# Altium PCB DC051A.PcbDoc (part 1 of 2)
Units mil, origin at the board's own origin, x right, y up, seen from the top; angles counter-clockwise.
Board outline 3200 x 2600 mil, 4 copper layers (L1-TOP, L2-GND, L3-POWER, L4-BOTTOM), stack 58.217 mil thick; 95 components, 55 nets, 249 pads, 164 vias.
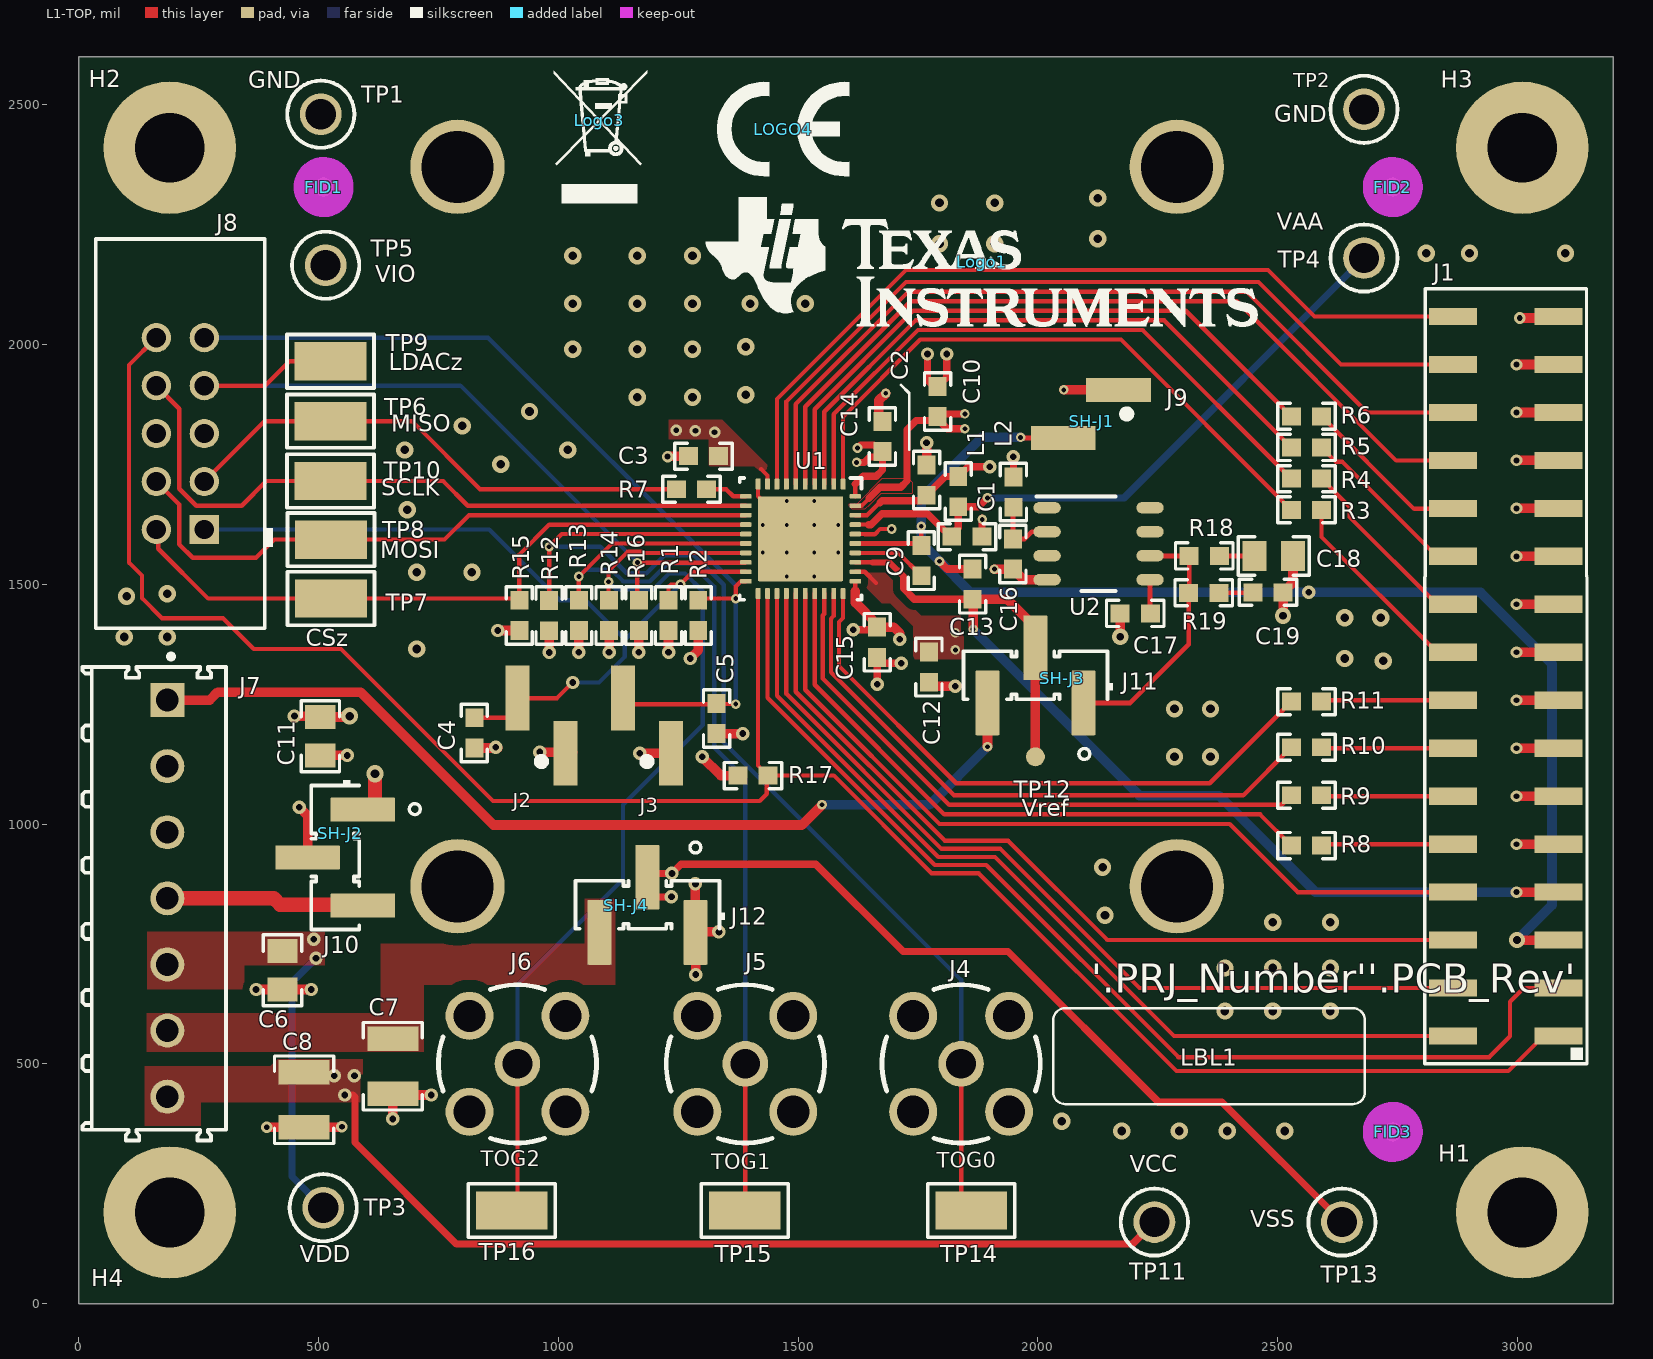
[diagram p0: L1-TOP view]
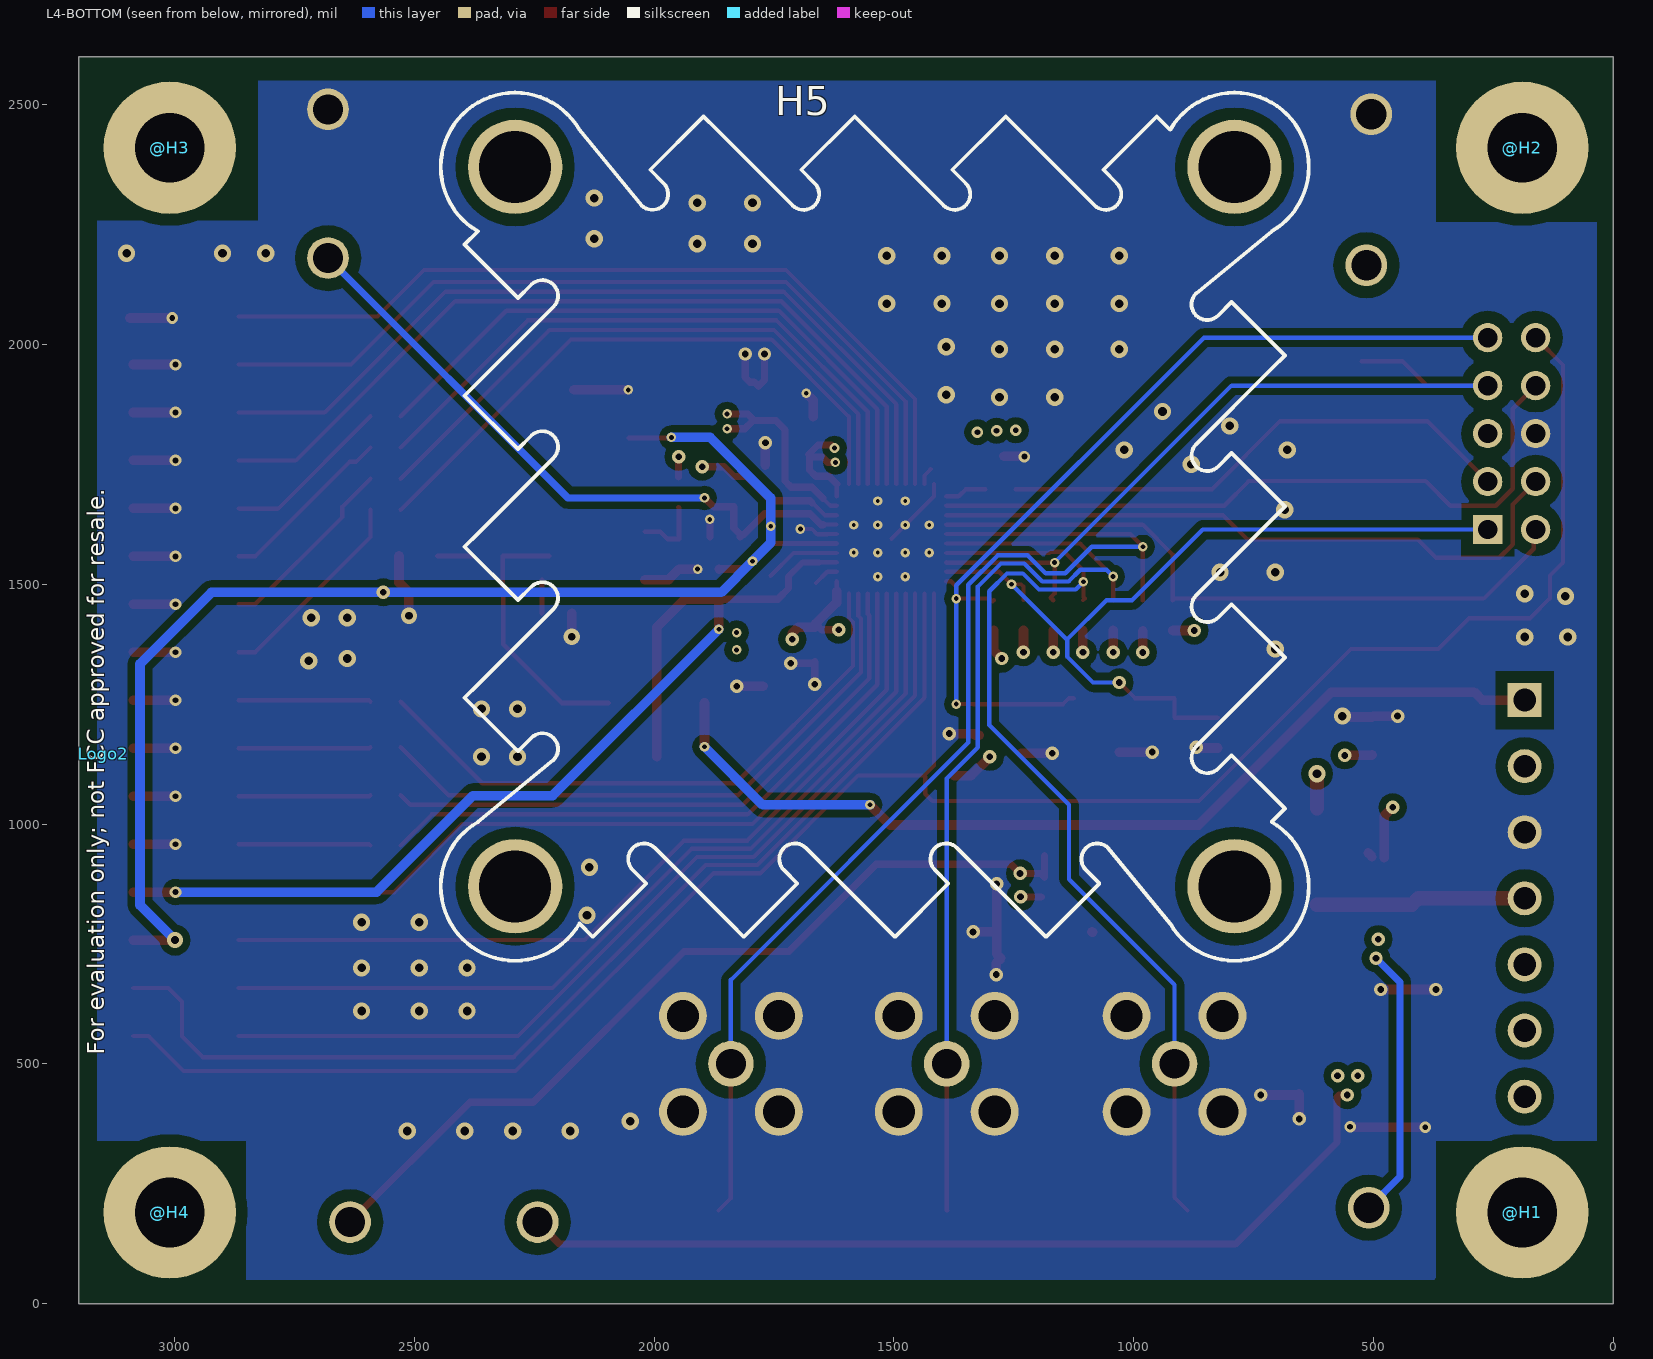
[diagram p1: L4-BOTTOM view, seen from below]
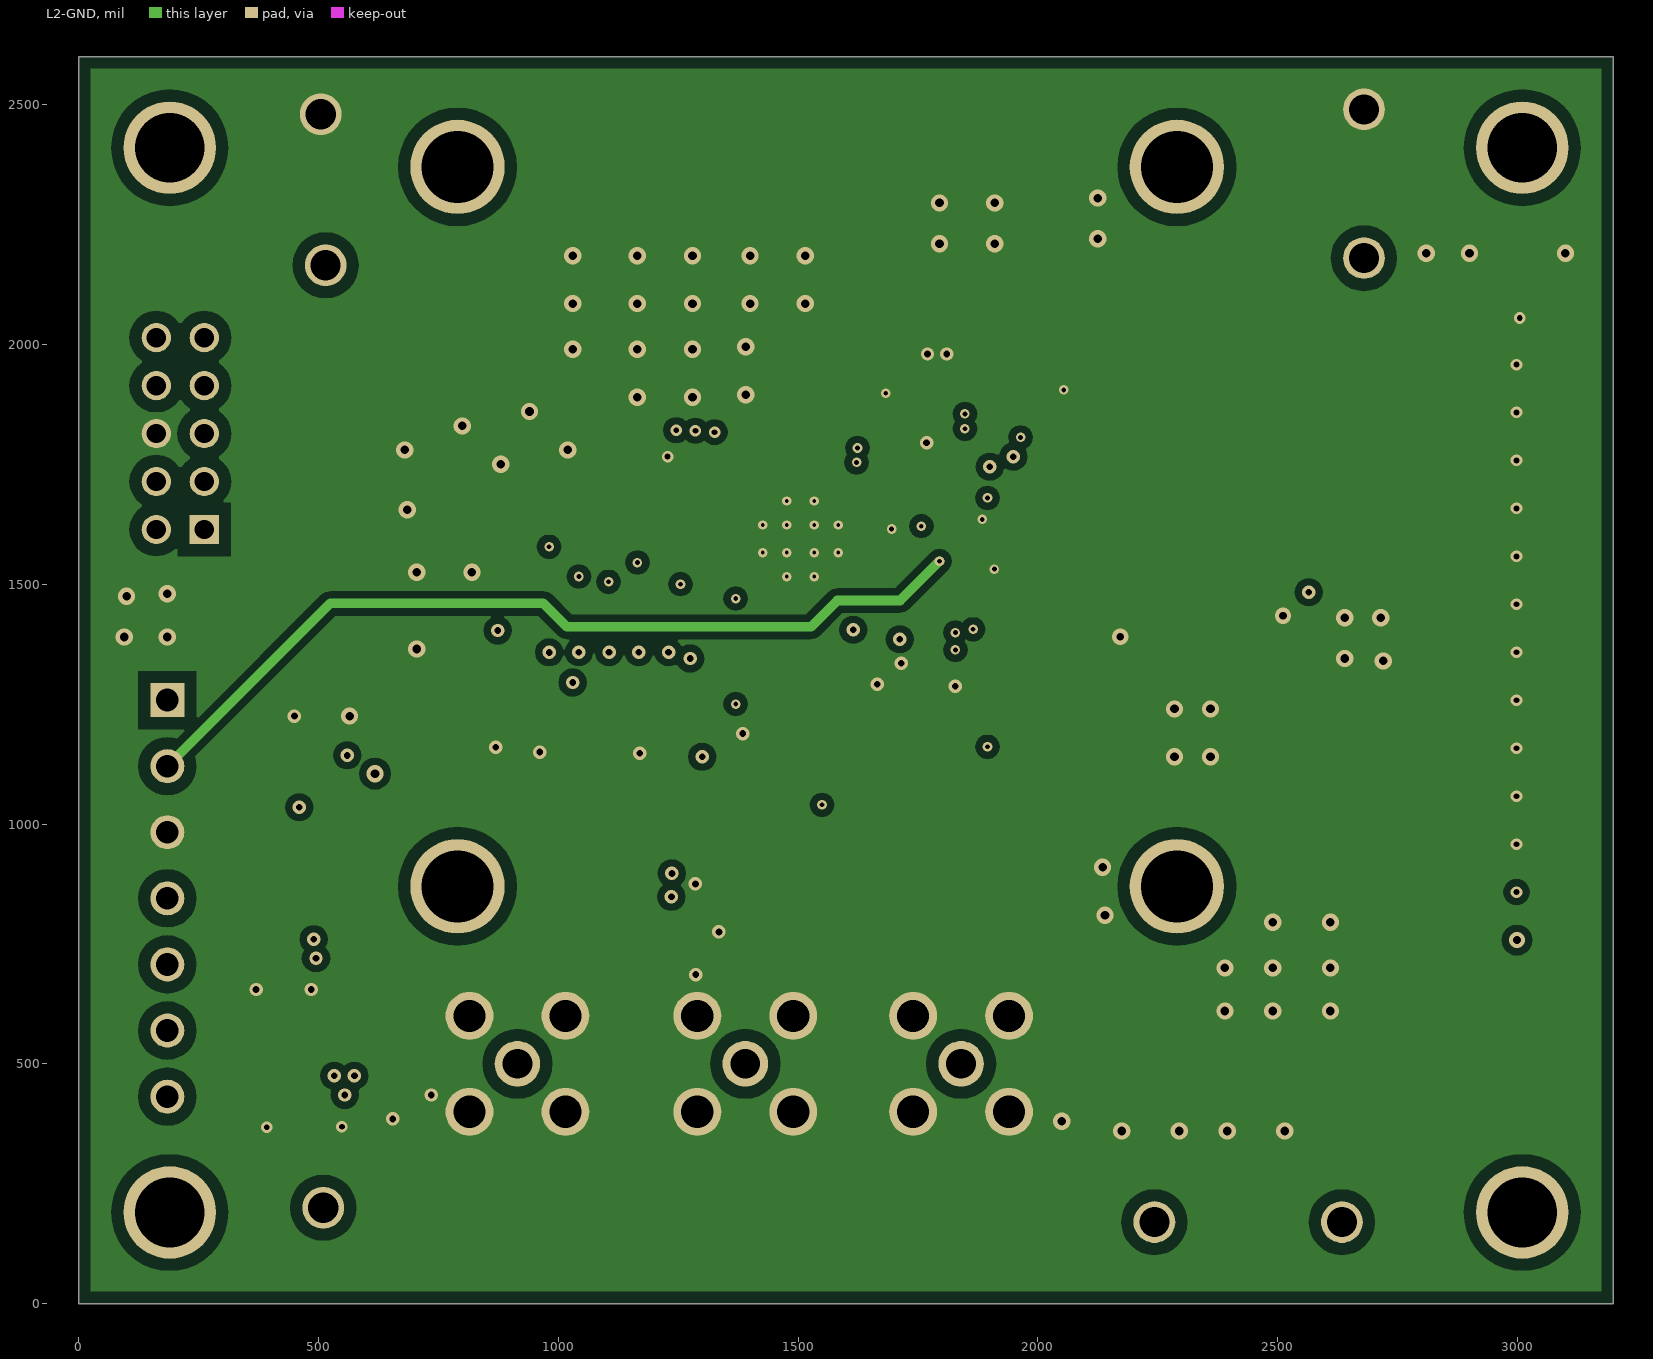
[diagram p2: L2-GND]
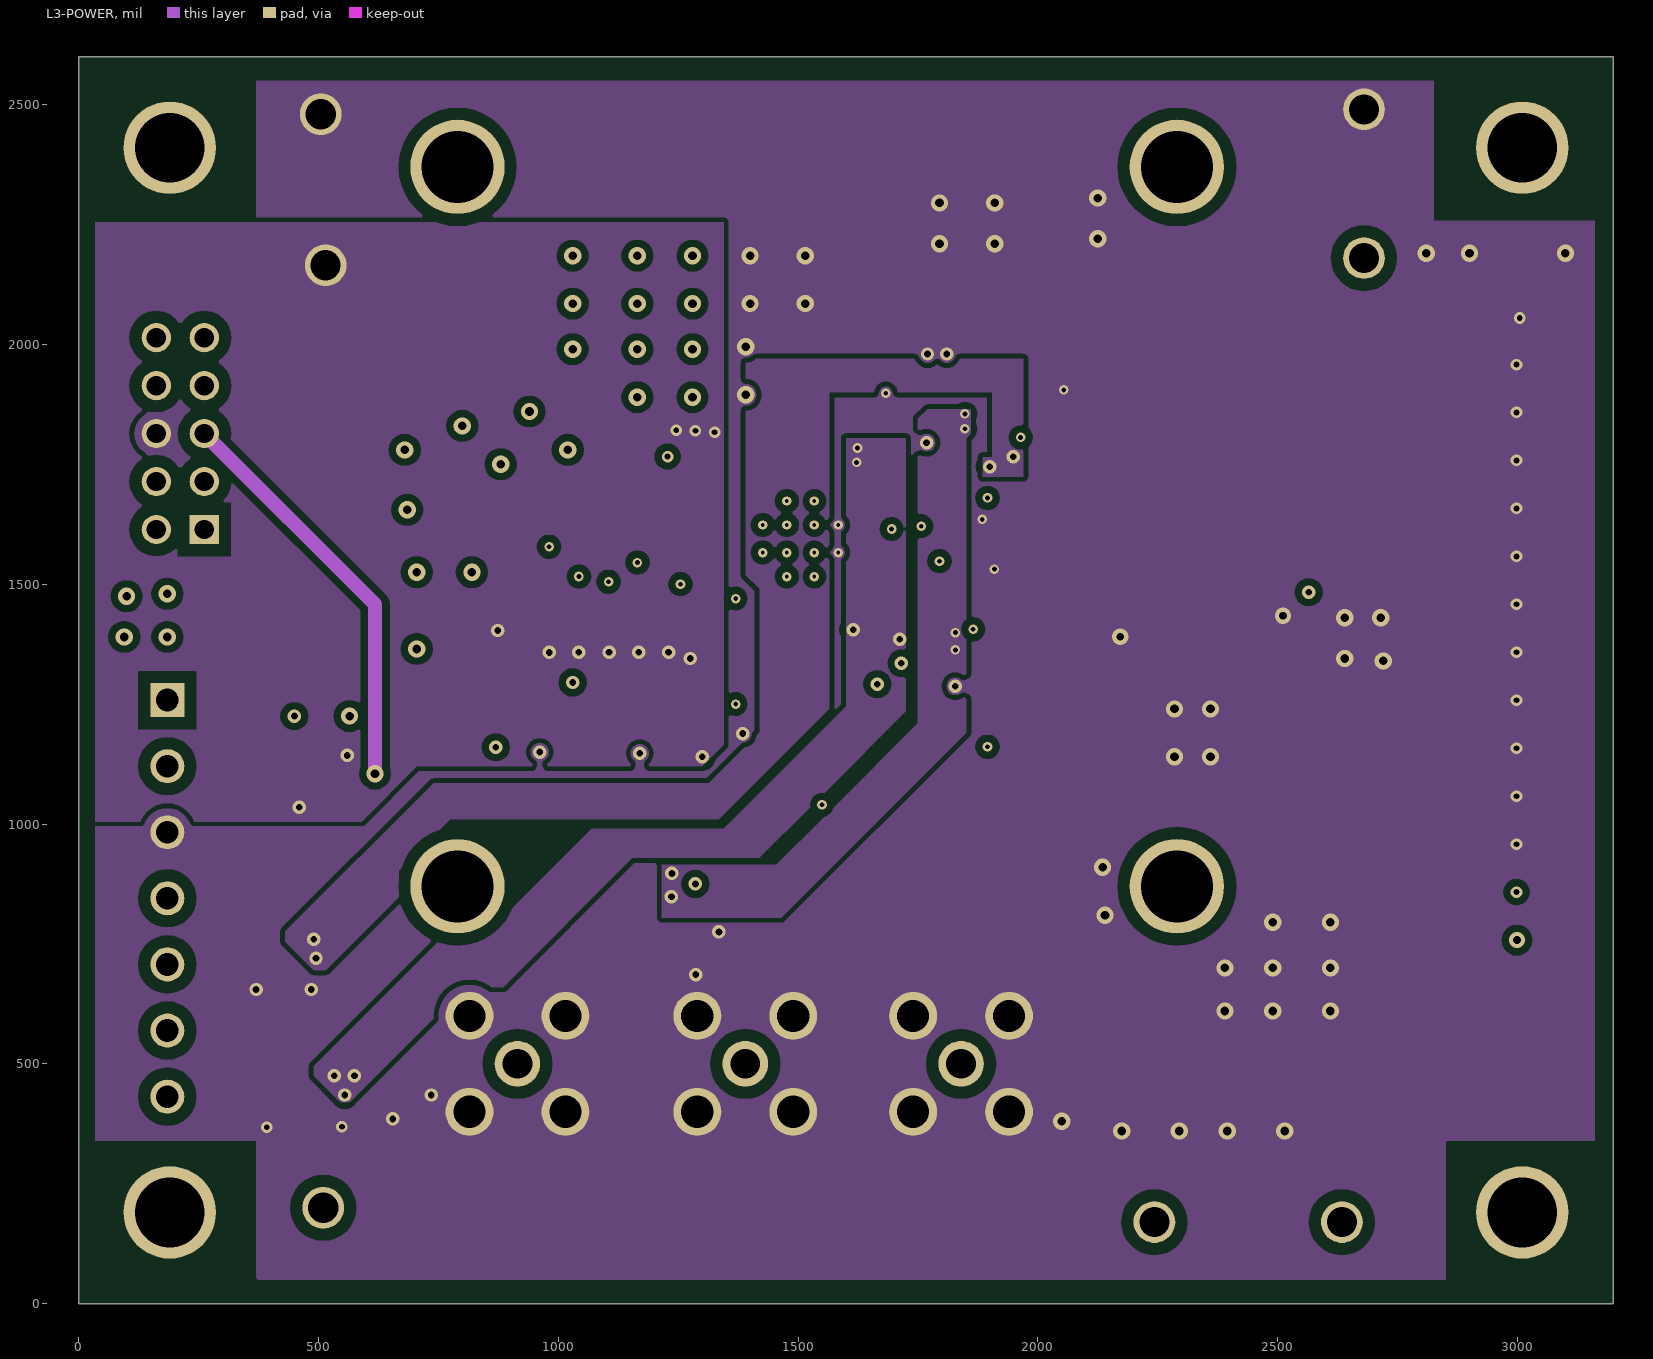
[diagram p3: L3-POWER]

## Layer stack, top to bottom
Top Solder: solder mask 0.4, Solder Resist, Dk 3.5
L1-TOP: signal copper 1.4
Dielectric1: core 10, FR-406, Dk 4.6
L2-GND: signal copper 1.417
Dielectric2: prepreg 32.6, FR-4, Dk 4.8
L3-POWER: signal copper 1.4
Dielectric3: core 10, FR-406, Dk 4.6
L4-BOTTOM: signal copper 1.4
Bottom Solder: solder mask 0.4, Solder Resist, Dk 3.5

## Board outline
0,0 0,2600 3200,2600 3200,0

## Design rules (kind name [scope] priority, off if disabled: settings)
AcuteAngle [All] p1: minimum=4.50000000000000E+0001 checktracksonly=FALSE
AssemblyTestPointUsage [All] p1: valid=2
BoardOutlineClearance BoardOutlineClearance_MountingHoles [OnCopper and InComponentClass('Mounting Holes')] p1: gap=40 ignorepadtopadclearanceinfootprint=FALSE
BoardOutlineClearance BoardOutlineClearance_Poly [OnCopper and IsPoly] p2: gap=25 ignorepadtopadclearanceinfootprint=FALSE
BoardOutlineClearance [OnCopper and Not InComponentClass('Logo') and not InComponentClass('FiducialMark') and not InRegion(1000,500,4000,800) and not InPoly] p3: gap=40 ignorepadtopadclearanceinfootprint=FALSE
Clearance Clearance_Keepouts [((IsTrack Or IsArc) And Not InPoly) And IsFree and IsKeepOut vs ((IsTrack Or IsArc) And Not InPoly) And IsFree and IsKeepOut] p1: gap=0 ignorepadtopadclearanceinfootprint=FALSE
Clearance Clearance_Poly [InPolygon] p2: gap=25 ignorepadtopadclearanceinfootprint=FALSE except(0: Arc-Hole Track-Hole SMDPad-Hole THPad-Hole Via-Hole Fill-Hole Poly-Hole Region-Hole Text-Hole; 10: Poly-Poly; 15: Track-Poly SMDPad-Poly Via-Poly)
Clearance [All] p3: gap=7.87 ignorepadtopadclearanceinfootprint=FALSE except(0: Arc-SMDPad Arc-Hole Track-Hole SMDPad-Hole THPad-Hole Via-Hole Fill-Hole Poly-Hole Region-Hole Text-Hole)
ComponentClearance ComponentClearance_MountingHoles_FiducialMarks [InComponentClass('Mounting Holes') vs InComponentClass('FiducialMark')] p1: gap=0 collisioncheckmode=3 verticalgap=10 showdistances=FALSE
ComponentClearance ComponentClearance_Shunt [InComponentClass('Header') vs InComponentClass('Shunt')] p2: gap=0 collisioncheckmode=3 verticalgap=0 showdistances=FALSE
ComponentClearance ComponentClearance_Logo [InComponentClass('Logo')] p3: gap=40 collisioncheckmode=3 verticalgap=10 showdistances=FALSE
ComponentClearance ComponentClearance_ScrewToNut [(HasFootprint('NY PMS 440 0025 PH')) vs (HasFootprint('Keystone_1902C'))] p4: gap=0 collisioncheckmode=3 verticalgap=0 showdistances=FALSE
ComponentClearance ComponentClearance_MountingHoles [InComponentClass('Mounting Holes')] p5: gap=0 collisioncheckmode=3 verticalgap=100000 showdistances=FALSE
ComponentClearance ComponentClearance_SmallPassives [HasFootprint('0201*') or HasFootprint('0402*') or HasFootprint('0508') or HasFootprint('0603*') or HasFootprint('0612') or HasFootprint('0805*') or HasFootprint('0815*') or HasFootprint('0830*') or HasFootprint('1206*') or HasFootprint('1210*') or HasFootprint('1808*') or HasFootprint('1812*') or HasFootprint('1825*') or HasFootprint('2010*') or HasFootprint('2220*') or HasFootprint('2225*') or HasFootprint('2512*') or HasFootprint('2728*') or HasFootprint('3518*') or HasFootprint('NY PMS 440 0025 PH') vs HasFootprint('0201*') or HasFootprint('0402*') or HasFootprint('0508') or HasFootprint('0603*') or HasFootprint('0612') or HasFootprint('0805*') or HasFootprint('0815*') or HasFootprint('0830*') or HasFootprint('1206*') or HasFootprint('1210*') or HasFootprint('1808*') or HasFootprint('1812*') or HasFootprint('1825*') or HasFootprint('2010*') or HasFootprint('2220*') or HasFootprint('2225*') or HasFootprint('2512*') or HasFootprint('2728*') or HasFootprint('3518*') or HasFootprint('Keystone_1902C')] p6: gap=14.96 collisioncheckmode=3 verticalgap=10 showdistances=FALSE
ComponentClearance ComponentClearance_THtoSMT [IsThruComponent vs IsSMTComponent] p7: gap=0 collisioncheckmode=3 verticalgap=0 showdistances=FALSE
ComponentClearance ComponentClearance_THtoTH [IsThruComponent vs IsThruComponent] p8: gap=30 collisioncheckmode=3 verticalgap=30 showdistances=FALSE
ComponentClearance [All] p9: gap=0 collisioncheckmode=3 verticalgap=10 showdistances=FALSE
DiffPairsRouting [All] p1: maxlimit=100 minlimit=10 mostfreqgap=10 toplayer_minwidth=15 toplayer_maxwidth=15 toplayer_prefwidth=15 midlayer1_minwidth=15 midlayer1_maxwidth=15 midlayer1_prefwidth=15 midlayer2_minwidth=15 midlayer2_maxwidth=15 midlayer2_prefwidth=15 bottomlayer_minwidth=15 bottomlayer_maxwidth=15 bottomlayer_prefwidth=15 maxuncoupledlength=1000
FabricationTestPointUsage TestPointUsage [All] p1: valid=2 allowmultiple=FALSE
FabricationTestpoint Testpoint [All] p1: side=3 testpointundercomponent=TRUE minsize=40 maxsize=100 preferedsize=60 minholesize=0 maxholesize=40 preferedholesize=32 testpointgrid=1 allowsidetop=TRUE allowsidebottom=TRUE usegrid=TRUE gridtolerance=0.01
FanoutControl Fanout_LCC [IsLCC] p1: bgadir=Out bgaviamode=Centered fanoutstyle=Auto fanoutdirection=Alternating viagrid=1 // Fanout_LCC (Default Rule)
FanoutControl Fanout_BGA [IsBGA] p2: bgadir=Out bgaviamode=Centered fanoutstyle=Auto fanoutdirection=Alternating viagrid=1 // Fanout_BGA (Default Rule)
FanoutControl Fanout_Default [All] p4: bgadir=Out bgaviamode=Centered fanoutstyle=Auto fanoutdirection=Alternating viagrid=1 // Fanout_Default (Default Rule)
FanoutControl Fanout_Small [(CompPinCount < 5)] p5: bgadir=Out bgaviamode=Centered fanoutstyle=Auto fanoutdirection=OutThenIn viagrid=1 // Fanout_Small (Default Rule)
Height [All] p1: minheight=0 maxheight=1400 prefheight=500
HoleSize [All] p1: absolutevalues=TRUE maxlimit=251 minlimit=7.87 maxpercent=80.000 minpercent=20.000
MinimumAnnularRing MinimumAnnularRing_ThermalPadVias [IsVia and InAnyComponent] p1: minimumring=5.91
MinimumAnnularRing [All] p2: minimumring=4
MinimumSolderMaskSliver MinimumSolderMaskSliver_Logo [InComponentClass('Logo') vs InComponentClass('Logo')] p1: minsoldermaskwidth=0.7
MinimumSolderMaskSliver [All] p2: minsoldermaskwidth=3.94
PlaneConnect [All] p1: planeconnectstyle=Relief reliefexpansion=10 reliefentries=4 reliefconductorwidth=10 reliefairgap=10
PolygonConnect [All] p1: connectstyle=Direct reliefconductorwidth=10 reliefentries=4 polygonreliefangle="90 Angle" airgapwidth=10
RoutingVias ThermalPadVias [IsVia and InAnyComponent] p1: holewidth=7.87 width=19.68 viastyle="Through Hole" minholewidth=7.87 minwidth=19.68 maxholewidth=12.99 maxwidth=23.62
RoutingVias [All] p2: holewidth=16 width=34 viastyle="Through Hole" minholewidth=7.87 minwidth=20 maxholewidth=40 maxwidth=65
SilkToBoardRegionClearance [Not ((IsComment or IsDesignator) And (Hide <> 'False')) and not InRegion(1000,500,4000,800)] p1:
SilkToSilkClearance SilkToSilkClearance_Pb-FreeLogo [(HasFootprint('Pb-Free_Overlay_Medium') OR HasFootprint('Pb-Free_Overlay_Small')) vs (HasFootprint('Pb-Free_Overlay_Medium') OR HasFootprint('Pb-Free_Overlay_Small'))] p1: silktosilkclearance=0
SilkToSilkClearance [All] p2: silktosilkclearance=3
SilkToSolderMaskClearance SilkToComponentPadClearance [(IsPad or IsFill or IsRegion) and InAnycomponent] p1: minsilkscreentomaskgap=3 clearancetoexposedcopper=TRUE
SilkToSolderMaskClearance "Silk to Solder Mask Opening" [All] p2: minsilkscreentomaskgap=3 clearancetoexposedcopper=FALSE
SolderMaskExpansion [All] p1: expansion=1.97
Width [All] p1: maxlimit=100 minlimit=6 preferedwidth=10 checkconnectedcopper=TRUE
14 further rules are at their usual default settings.

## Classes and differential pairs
component class Label: LBL1
component class DC051A_EVM_Hardware: !PCB @H1 @H2 @H3 @H4 FID1 FID2 FID3 H1 H2 H3 H4 H5 LBL1 Logo1 Logo2 Logo3 LOGO4 Logo4 LOGO? Logo? SH-J1 SH-J2 SH-J3 SH-J4 ZZ1 ZZ2 ZZ3 ZZ4
component class DC051A: C1 C2 C3 C4 C5 C6 C7 C8 C9 C10 C11 C12 C13 C14 C15 C16 C17 C18 C19 GND J1 J2 J3 J4 J5 J6 J7 J8 J9 J10 J11 J12 L1 L2 R1 R2 R3 R4 R5 R6 R7 R8 R9 R10 R11 R12 R13 R14 R15 R16 R17 R18 R19 TP1 TP2 TP3 TP4 TP5 TP6 TP7 TP8 TP9 TP10 TP11 TP12 TP13 TP14 TP15 TP16 U1 U2
component class Logo: Logo1
component class Header: J1 J2 J3 J9 J10 J11 J12
component class AssemblyNote: ZZ1 ZZ2 ZZ3 ZZ4
component class FiducialMark: FID1 FID2 FID3
component class Shunt: SH-J1 SH-J2 SH-J3 SH-J4

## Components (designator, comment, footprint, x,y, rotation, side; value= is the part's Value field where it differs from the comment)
@H1 "1891" Keystone_1891 190,190 r180 bottom
@H2 "1891" Keystone_1891 190,2410 r180 bottom
@H3 "1891" Keystone_1891 3010,2410 r180 bottom
@H4 "1891" Keystone_1891 3010,190 r180 bottom
C1 "C0603C105K4PACTU" 0603 1852,1599 r0 top value=1uF
C2 "C0603C104J4RACTU" 0603 1768,1717 r90 top value=0.1uF
C3 "C0603C104J4RACTU" 0603 1303,1767 r180 top value=0.1uF
C4 "C0603C105K4PACTU" 0603 825,1190 r270 top value=1uF
C5 "C0603C105K4PACTU" 0603 1330,1220 r270 top value=1uF
C6 "GRM21BC8YA106KE11L" 0805_HV 425,695 r270 top value=10uF
C7 "UMJ325KB7106KMHT" 1210_270 655,495 r270 top value=10uF
C8 "UMJ325KB7106KMHT" 1210_270 470,425 r270 top value=10uF
C9 "C0603C102K5RACTU" 0603 1757,1549 r90 top value=1000pF
C10 "C0603C105K4PACTU" 0603 1791,1881 r90 top value=1uF
C11 "GRM21BC8YA106KE11L" 0805_HV 504,1183 r90 top value=10uF
C12 "C0603C105K4PACTU" 0603 1773,1327 r270 top value=1uF
C13 "C0603C104J4RACTU" 0603 1864,1500 r90 top value=0.1uF
C14 "C0603C105K4PACTU" 0603 1676,1808 r90 top value=1uF
C15 "C0603C105K4PACTU" 0603 1665,1379 r270 top value=1uF
C16 "C1608X5R1E105K080AC" 0603 1948,1563 r270 top value=1uF
C17 "C1608X5R1E105K080AC" 0603 2203,1439 r180 top value=1uF
C18 "GRM21BC8YA106KE11L" 0805_HV 2492,1559 r0 top value=10uF
C19 "C1608X5R1E105K080AC" 0603 2480,1483 r0 top value=1uF
FID1 "Fiducial" Fiducial10-30 511,2328 r180 top
FID2 "Fiducial" Fiducial10-30 2740,2328 r180 top
FID3 "Fiducial" Fiducial10-30 2740,358 r180 top
H1 "29311" Keystone29311 3010,190 r0 top
H2 "29311" Keystone29311 190,2410 r0 top
H3 "29311" Keystone29311 3010,2410 r0 top
H4 "29311" Keystone29311 190,190 r0 top
H5 "500403B00000G" Aavid_500403B00000G 1540,1620 r0 bottom
J1 "TSM-116-01-T-DV-P" CONN_TSM-116-01-T-DV-P 2976,1308 r90 top
J2 "TSM-102-01-L-SV" Samtec_TSM-102-01-L-SV 965,1205 r180 top
J3 "TSM-102-01-L-SV" Samtec_TSM-102-01-L-SV 1185,1205 r180 top
J4 "142-0701-231" Johnson_142-0701-231 1840,500 r270 top
J5 "142-0701-231" Johnson_142-0701-231 1389.99,500 r180 top
J6 "142-0701-231" Johnson_142-0701-231 915,500 r90 top
J7 "1984662" Phoenix_1984662 185,845 r270 top locked
J8 "AWHW-10G-0202-T" Assman_AWHW-10G-0x02-T 212,1814 r180 top
J9 "TSM-102-01-L-SV" Samtec_TSM-102-01-L-SV 2110.52,1855 r270 top
J10 "TSM-103-01-L-SV-P-TR" Samtec_TSM-103-01-x-SV-P 535,930 r270 top
J11 "TSM-103-01-L-SV-P-TR" Samtec_TSM-103-01-x-SV-P 1995,1310 r180 top
J12 "TSM-103-01-L-SV-P-TR" Samtec_TSM-103-01-x-SV-P 1186,831.5 r180 top
L1 "742792651" 0603 1834,1693 r270 top value="600 ohm"
L2 "742792651" 0603 1949,1692 r270 top value="600 ohm"
LBL1 "THT-14-423-10" Label_650x200 2357,516 r0 top
Logo1 "Texas Instruments" TI_Stacked_Overlay_Medium 1883,2172 r0 top
Logo2 "FCC disclaimer" FCC_disclaimer 3149,1146 r90 bottom
Logo3 "WEEE logo" WEEE_Minimum 1086,2467 r0 top
LOGO4 "CE Mark" CE_Mark_5mm 1469,2449 r0 top
R1 "RC0603FR-0710KL" 0603 1230,1435 r270 top value=10.0k
R2 "RC0603FR-0710KL" 0603 1292,1435 r270 top value=10.0k
R3 "RC0603JR-070RL" 0603 2560,1655 r0 top value=0
R4 "RC0603JR-070RL" 0603 2560,1720 r0 top value=0
R5 "RC0603JR-070RL" 0603 2560,1785 r0 top value=0
R6 "RC0603JR-070RL" 0603 2560,1850 r0 top value=0
R7 "CRCW060333R0JNEA" 0603 1278,1698 r0 top value=33
R8 "RC0603JR-070RL" 0603 2560,955 r0 top value=0
R9 "RC0603JR-070RL" 0603 2560,1060 r0 top value=0
R10 "RC0603JR-070RL" 0603 2560,1160 r0 top value=0
R11 "RC0603JR-070RL" 0603 2560,1255 r0 top value=0
R12 "RC0603FR-0710KL" 0603 981,1434.5 r90 top value=10.0k
R13 "RC0603FR-0710KL" 0603 1043,1435 r90 top value=10.0k
R14 "RC0603FR-0710KL" 0603 1106,1435 r90 top value=10.0k
R15 "RC0603FR-0710KL" 0603 919,1435 r90 top value=10.0k
R16 "RC0603FR-0710KL" 0603 1168,1435 r90 top value=10.0k
R17 "RC0603FR-0710KL" 0603 1406,1101 r0 top value=10.0k
R18 "ERJ-3RQFR51V" 0603 2347,1559 r180 top value=0.51
R19 "RC0603FR-071RL" 0603 2346,1482 r180 top value=1.00
SH-J1 "SNT-100-BK-G" SNT-100-BK-G 2112,1840 r90 top value=1x2
SH-J2 "SNT-100-BK-G" SNT-100-BK-G 546,981 r90 top value=1x2
SH-J3 "SNT-100-BK-G" SNT-100-BK-G 2051,1304 r180 top value=1x2
SH-J4 "SNT-100-BK-G" SNT-100-BK-G 1142,831 r180 top value=1x2
TP1 "5005" Keystone5005 505,2480 r270 top
TP2 "5005" Keystone5005 2680,2490 r270 top
TP3 "5005" Keystone5005 510,200 r180 top
TP4 "5005" Keystone5005 2680,2180 r180 top
TP5 "5005" Keystone5005 515,2165 r270 top
TP6 "5019" Keystone_5019 525,1840 r180 top
TP7 "5019" Keystone_5019 526,1470 r0 top
TP8 "5019" Keystone_5019 526,1593 r0 top
TP9 "5019" Keystone_5019 525,1965 r180 top
TP10 "5019" Keystone_5019 525,1715 r180 top
TP11 "5005" Keystone5005 2243,170 r180 top
TP12 "TP_SM_1MM" TP_SM_1MM 1995,1140 r180 top locked
TP13 "5005" Keystone5005 2634,170 r0 top
TP14 "5019" Keystone_5019 1861,194 r180 top
TP15 "5019" Keystone_5019 1389,194 r0 top
TP16 "5019" Keystone_5019 903,194 r0 top
U1 "DAC81416RHA" RHA0040H 1505.28,1594.7 r270 top
U2 "REF5025AIDR" D0008A_N 2126.65,1584.34 r0 top
ZZ1 "Install label in silkscreened box after final wash.  Text shall be 8 pt font.  Text shall be per the Label Table in the PDF schematic." AssemblyNote 218,3663 r0 top
ZZ2 "These assemblies are ESD sensitive, ESD precautions shall be observed." AssemblyNote 218,3570 r0 top
ZZ3 "These assemblies must be clean and free from flux and all contaminants. Use of no clean flux is not acceptable." AssemblyNote 218,3490 r0 top
ZZ4 "These assemblies must comply with workmanship standards IPC-A-610 Class 2, unless otherwise specified." AssemblyNote 218,3402 r0 top

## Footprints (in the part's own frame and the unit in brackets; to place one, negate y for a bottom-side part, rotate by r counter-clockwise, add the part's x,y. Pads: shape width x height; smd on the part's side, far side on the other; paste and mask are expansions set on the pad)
0603 [mm] "0603 from SM-752 data"
  rect 1x0.95 smd: 1(-0.8,0) 2(0.8,0)
  silkscreen extent -1.52,-0.69 1.52,0.69, body extent -0.87,-0.47 0.87,0.47, height 1
0805_HV [mil] "0805 with 30mil clearance between pads"
  rect 50x63 smd: 1(-40,0) 2(40,0)
  silkscreen extent -74,-40 74,40, body extent -43,-29 43,29, height 57
1210_270 [mm] "1210"
  rect 1.3x2.7 smd: 1(-1.45,0) 2(1.45,0)
  silkscreen extent -2.32,-1.57 2.32,1.57, body extent -1.7,-1.35 1.7,1.35, height 2.7
Aavid_500403B00000G [mm] "Heat Sink TO-3 Aluminum"
  round 5 hole 3.81: MH1(-19.05,19.05) MH2(19.05,19.05) MH3(-19.05,-19.05) MH4(19.05,-19.05)
  silkscreen extent -22.99,-22.99 22.99,22.99, body extent -22.98,-22.98 22.98,22.98, height 31.75
AssemblyNote [mil] "Assembly Note"
Assman_AWHW-10G-0x02-T [mm] "Header, 2.54mm, 5x2, TH"
  rect 1.55x1.55 hole 1.02: 1(-1.27,5.08)
  round 1.55 hole 1.02: 2(1.27,5.08) 3(-1.27,2.54) 4(1.27,2.54) 5(-1.27,0) 6(1.27,0) 7(-1.27,-2.54) 8(1.27,-2.54) 9(-1.27,-5.08) 10(1.27,-5.08)
  silkscreen extent -4.9,-10.31 4.47,10.31, body extent -4.47,-10.31 4.47,10.31, height 9.15
CE_Mark_5mm [mil] "Minimum text height for CE Mark"
  silkscreen extent -138,-98 138,98
CONN_TSM-116-01-T-DV-P [mil] "Samtec"
  rect 36x100 smd: 1(-750,-110) 2(-750,110) 3(-650,-110) 4(-650,110) 5(-550,-110) 6(-550,110) 7(-450,-110) 8(-450,110) 9(-350,-110) 10(-350,110) 11(-250,-110) 12(-250,110) 13(-150,-110) 14(-150,110) 15(-50,-110) 16(-50,110) 17(50,-110) 18(50,110) 19(150,-110) 20(150,110) 21(250,-110) 22(250,110) 23(350,-110) 24(350,110) 25(450,-110) 26(450,110) 27(550,-110) 28(550,110) 29(650,-110) 30(650,110) 31(750,-110) 32(750,110)
  silkscreen extent -808,-169 808,169, body extent -800,-145 800,145, height 380
D0008A_N [mm] "SOIC, 8-Leads, Body 4.9x3.9mm, Pitch 1.27mm, IPC Medium Density"
  oval 1.45x0.6 smd: 1(-2.725,1.905) 2(-2.725,0.635) 3(-2.725,-0.635) 4(-2.725,-1.905) 5(2.725,-1.905) 6(2.725,-0.635) 7(2.725,0.635) 8(2.725,1.905)
  silkscreen extent -3.3,-2.5 0.9,2.5, body extent -3,-2.45 3,2.45, height 1.63
FCC_disclaimer [mil]
Fiducial10-30 [mm]
  round 1 smd mask+1: 1(0,0)
  L1-TOP keep-out circle w1.678: c0,0 r0.75
Johnson_142-0701-231 [mil] "Johnson Components recommended land pattern"
  round 95 hole 62: 1(0,0)
  round 100 hole 67: 2(100,100) 3(100,-100) 4(-100,-100) 5(-100,100)
  silkscreen extent -165,-165 165,165, body extent -156,-156 156,156, height 375
Keystone5005 [mil] "Keystone Compact loops"
  round 87 hole 63: 1(0,0)
  silkscreen extent -70,-70 70,70, body extent -63,-63 62,63, height 225
Keystone29311 [mm] "Srcew, Pan HeadM5x0.5 mm, Zinc Plated  6.0mm L"
  round 7 / inner round 4.9 / far side round 7 hole 3.7: 1(0,0)
  body extent -2.7,-2.7 2.7,2.7, height 1.72
Keystone_1891 [mil] "3/16 Hex Female Standoff"
  body extent -108,-93 108,94, height 245
Keystone_5019 [mm] "Test Point, Miniature, SMT"
  rect 3.8x2.03 smd: 1(0,0)
  silkscreen extent -2.31,-1.42 2.31,1.42, body extent -1.9,-1.02 1.9,1.02, height 2.29
Label_650x200 [mil] "Thermal Transfer Label"
  round 1 on Mech13: 0(0,0)
  silkscreen extent -325,-100 325,100, body extent -325,-100 325,100, height 1
Phoenix_1984662 [mm] "PHOENIX CONTACT"
  rect 1.8x1.8 hole 1.2: 1(-10.5,0)
  round 1.8 hole 1.2: 2(-7,0) 3(-3.5,0) 4(0,0) 5(3.5,0) 6(7,0) 7(10.5,0)
  silkscreen extent -12.82,-4.5 12.82,3.1, body extent -12.25,-4.5 12.82,3.1, height 9.02
RHA0040H [mm] "QFN, 40-Leads, Body 6x6mm, Pitch 0.5mm, Thermal Pad 4.15 x 4.15mm, TI Recommended"
  rrect40% 0.6x0.25 smd: 1(-2.9,2.25) 2(-2.9,1.75) 3(-2.9,1.25) 4(-2.9,0.75) 5(-2.9,0.25) 6(-2.9,-0.25) 7(-2.9,-0.75) 8(-2.9,-1.25) 9(-2.9,-1.75) 10(-2.9,-2.25) 21(2.9,-2.25) 22(2.9,-1.75) 23(2.9,-1.25) 24(2.9,-0.75) 25(2.9,-0.25) 26(2.9,0.25) 27(2.9,0.75) 28(2.9,1.25) 29(2.9,1.75) 30(2.9,2.25)
  rrect40% 0.25x0.6 smd: 11(-2.25,-2.9) 12(-1.75,-2.9) 13(-1.25,-2.9) 14(-0.75,-2.9) 15(-0.25,-2.9) 16(0.25,-2.9) 17(0.75,-2.9) 18(1.25,-2.9) 19(1.75,-2.9) 20(2.25,-2.9) 31(2.25,2.9) 32(1.75,2.9) 33(1.25,2.9) 34(0.75,2.9) 35(0.25,2.9) 36(-0.25,2.9) 37(-0.75,2.9) 38(-1.25,2.9) 39(-1.75,2.9) 40(-2.25,2.9)
  rrect8% 1.26x1.26 on Top Paste: 41(-1.46,1.46) 41(-1.46,0) 41(-1.46,-1.46) 41(0,1.46) 41(0,0) 41(0,-1.46) 41(1.46,1.46) 41(1.46,0) 41(1.46,-1.46)
  rrect2% 4.5x4.5 smd paste-2.5: 41(0,0)
  silkscreen extent -3.22,-3.22 3.22,3.23, body extent -3,-3 3,3, height 1
Samtec_TSM-102-01-L-SV [mm] "SAMTEC"
  rect 1.27x3.43 smd: 1(-1.27,1.46) 2(1.27,-1.46)
  silkscreen extent -0.2,1.7 0.2,2.1, body extent -2.53,-2.45 2.55,2.45, height 9.65
Samtec_TSM-103-01-x-SV-P [mm] "Header, 2.54mm, 3x1, SMT"
  rrect8% 1.27x3.43 smd: 1(-2.54,1.46) 2(0,-1.46) 3(2.54,1.46)
  silkscreen extent -4.1,-1.27 3.81,1.27, body extent -3.81,-2.41 3.81,2.41, height 9.97
SNT-100-BK-G [mil] "Samtec STEP model"
  round 1 on Mech3: 0(0,0)
  body extent -100,-50 100,50, height 344
TI_Stacked_Overlay_Medium [mil]
  silkscreen extent -576,-136 576,134
TP_SM_1MM [mm] "1mm Test Point, SMT"
  round 1 smd paste-0.5: 1(0,0)
WEEE_Minimum [mil] "WEEElie bin"
  silkscreen extent -95,-172 99,104

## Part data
@H1 @H2 @H3 @H4: library part CMP-0003792-1, "Hex Standoff, #4-40, Aluminum, 1/4\"", Manufacturer=Keystone, Supplier Part Number 1=36-1891-ND
C1 C4 C5 C10 C12 C14 C15: library part CMP-0006868-5, "CAP, CERM, 1 uF, 16 V, +/- 10%, X5R, 0603", Cap_Case=0603, Manufacturer=Kemet, Supplier Part Number 1=399-5090-1-ND, TempCo=X5R, Tolerance_%=10%, Value1=Unknown, Value2=16V, ValueDisplayed=1uF
C2 C3 C13: library part CMP-0006857-4, "CAP, CERM, 0.1 uF, 16 V, +/- 5%, X7R, 0603", Cap_Case=0603, Manufacturer=Kemet, Supplier Part Number 1=399-1097-1-ND, TempCo=X7R, Tolerance_%=5%, Value1=Unknown, Value2=16V, ValueDisplayed=0.1uF
C6 C11 C18: library part CMP-0008273-1, "CAP, CERM, 10 uF, 35 V, +/- 10%, X6S, 0805", Cap_Case=0805, Manufacturer=MuRata, Supplier Part Number 1=490-10504-1-ND, TempCo=X6S, Tolerance_%=10%, Value1=Unknown, Value2=35V, ValueDisplayed=10uF
C7 C8: library part CMP-0009257-2, "CAP, CERM, 10 uF, 50 V, +/- 10%, X7R, AEC-Q200 Grade 1, 1210", Cap_Case=1210, Manufacturer="Taiyo Yuden", Supplier Part Number 1=587-4279-1-ND, TempCo=X7R, Tolerance_%=10%, Value1=Unknown, Value2=50V, ValueDisplayed=10uF
C9: library part CMP-0006847-4, "CAP, CERM, 1000 pF, 50 V, +/- 10%, X7R, 0603", Cap_Case=0603, Manufacturer=Kemet, Supplier Part Number 1=399-1082-1-ND, TempCo=X7R, Tolerance_%=10%, Value1=Unknown, Value2=50V, ValueDisplayed=1000pF
C16 C17 C19: library part CMP-0007006-5, "CAP, CERM, 1 uF, 25 V, +/- 10%, X5R, 0603", Cap_Case=0603, Manufacturer=TDK, Supplier Part Number 1=445-5146-1-ND, TempCo=X5R, Tolerance_%=10%, Value1=Unknown, Value2=25V, ValueDisplayed=1uF
FID1 FID2 FID3: library part CMP-0077181-1, "Fiducial mark.  There is nothing to buy or mount.", Manufacturer=N/A
H1 H2 H3 H4: library part CMP-0003639-1, "Screw Pan Head M3", Manufacturer=Keystone, Supplier Part Number 1=36-29311-ND
H5: "Square Basket Heatsink Featuring Slanted Fins", Manufacturer=Aavid
J1: library part CMP-0075449-1, "Header, 100mil, 16x2, Tin, SMT", Manufacturer=Samtec, Supplier Part Number 1=TSM-116-01-T-DV-P-ND
J2 J3 J9: library part CMP-0075467-1, "Header, 100mil, 2x1, Gold with Tin Tail, SMT", Color=Black, Current_A=5.4A, Manufacturer=Samtec, Supplier Part Number 1=TSM-102-01-L-SV-ND, Voltage_V=475V
J4 J5 J6: library part CMP-0055820-1, "Connector, SMA, TH", Manufacturer="Cinch Connectivity", Supplier Part Number 1=J608-ND
J7: library part CMP-0055484-1, "TERM BLOCK, 7POS, 3.5MM, TH", Manufacturer="Phoenix Contact", Supplier Part Number 1=277-1861-ND
J8: library part CMP-0075161-1, "Header(Shrouded), 2.54mm, 5x2, Gold, TH", Color=Gray, Manufacturer="Assman WSW", Supplier Part Number 1=AWHW-10G-0202-T-ND
J10 J11 J12: library part CMP-0055592-1, "Header, 2.54mm, 3x1, Gold, SMT", Color=Black, Current_A=5.4A, Manufacturer=Samtec, Supplier Part Number 1=TSM-103-01-L-SV-P-TR-ND, Voltage_V=475V
L1 L2: library part CMP-0003197-2, "Ferrite Bead, 600 ohm @ 100 MHz, 1 A, 0603", Manufacturer="Wurth Elektronik", Supplier Part Number 1=732-1593-1-ND, Value1="0.2 ohm", Value2=1A, ValueDisplayed="600 ohm"
LBL1: library part CMP-0003625-1, "Thermal Transfer Printable Labels, 0.650\" W x 0.200\" H - 10,000 per roll", Manufacturer=Brady, Supplier Part Number 1=97C5133
Logo1: library part CMP-0074838-1, "Texas Instrument Corporate Signature"
Logo2: library part CMP-0074847-1, "FCC_disclaimer"
Logo3: library part CMP-0074769-1
LOGO4: library part CMP-0074844-1
R1 R2 R12 R13 R14 R15 R16 R17: library part CMP-0022746-3, "RES, 10.0 k, 1%, 0.1 W, 0603", Manufacturer="Yageo America", Power_W=100mW, Supplier Part Number 1=311-10.0KHRCT-ND, TempCo="200 ppm/C", Tolerance_%=1%, Value2=0.1W, Value_Code=10k0, ValueDisplayed=10.0k
R3 R4 R5 R6 R8 R9 R10 R11: library part CMP-0025885-3, "RES, 0, 5%, 0.1 W, 0603", Manufacturer="Yageo America", Power_W=100mW, Supplier Part Number 1=311-0.0GRCT-ND, TempCo="200 ppm/C", Tolerance_%=5%, Value2=0.1W, Value_Code=0000, ValueDisplayed=0
R7: library part CMP-0025787-4, "RES, 33, 5%, 0.1 W, AEC-Q200 Grade 0, 0603", Manufacturer=Vishay-Dale, Power_W=100mW, Supplier Part Number 1=541-33GCT-ND, TempCo="200 ppm/C", Tolerance_%=5%, Value2=0.1W, Value_Code=33R0, ValueDisplayed=33
R18: library part CMP-0022717-2, "RES, 0.51, 1%, 0.1 W, AEC-Q200 Grade 1, 0603", Manufacturer=Panasonic, Power_W=100mW, Supplier Part Number 1=P.51AJCT-ND, TempCo="300 ppm/C", Tolerance_%=1%, Value2=0.1W, Value_Code=R510, ValueDisplayed=0.51
R19: library part CMP-0022900-2, "RES, 1.00, 1%, 0.1 W, 0603", Manufacturer="Yageo America", Power_W=100mW, Supplier Part Number 1=311-1.00HRCT-ND, TempCo="200 ppm/C", Tolerance_%=1%, Value2=0.1W, Value_Code=1R00, ValueDisplayed=1.00
SH-J1 SH-J2 SH-J3 SH-J4: library part CMP-0003623-1, "Shunt, 100mil, Gold plated, Black", Alternate Manufacturer=3M, Alternate PartNumber=969102-0000-DA, Manufacturer=Samtec, Supplier Part Number 1=SNT-100-BK-G-ND
TP1 TP2 TP3 TP4 TP5 TP11 TP13: library part CMP-0055142-1, "Test Point, Compact, Red, TH", Color=Red, Manufacturer=Keystone, Supplier Part Number 1=36-5005-ND
TP6 TP7 TP8 TP9 TP10 TP14 TP15 TP16: library part CMP-0055162-1, "Test Point, Miniature, SMT", Manufacturer=Keystone, Supplier Part Number 1=36-5019TR-ND
TP12: library part CMP-0003825-1, "1mm Test Point, SMT", Manufacturer=Any
U1: library part CMP-0013795-3, "16-Channel, 16-Bit, High-Voltage Output DAC with Precision Internal Reference, RHA0040H (VQFN-40)", Alternate Manufacturer="Texas Instruments"
U2: library part CMP-0032581-1, "Low Noise, Very Low Drift, Precision Voltage Reference, -40 to 125 degC, 8-pin SOIC (D), Green (RoHS & no Sb/Br)", Manufacturer="Texas Instruments", Rating=Military, Temp Coeff(Max)(ppm/ degree C)=3
ZZ1 ZZ2 ZZ3 ZZ4: library part CMP-0003615-1

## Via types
v1: diameter 36, hole 18, L1-TOP to L4-BOTTOM, tented both sides, 64 vias
v2: diameter 28, hole 14, L1-TOP to L4-BOTTOM, tented both sides, 41 vias
v3: diameter 20, hole 10, L1-TOP to L4-BOTTOM, tented both sides, 25 vias
v4: diameter 24, hole 12, L1-TOP to L4-BOTTOM, tented both sides, 19 vias
v5: diameter 19.68, hole 7.87, L1-TOP to L4-BOTTOM, 12 vias
v6: diameter 34, hole 16, L1-TOP to L4-BOTTOM, 3 vias

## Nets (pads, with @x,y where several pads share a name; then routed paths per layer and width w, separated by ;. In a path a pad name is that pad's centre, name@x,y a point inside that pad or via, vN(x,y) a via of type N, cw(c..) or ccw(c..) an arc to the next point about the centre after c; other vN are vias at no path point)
ALMOUT_GPIO0: J1.1 J8.10 R17.2 U1.21 | length 4423.3
  L1-TOP w9: J8.10@162,2014 105,1957 105,1545 132,1518 132,1471 174,1429 301,1429 365,1365 547,1365 864,1048 1420,1048 1435,1063 1435,1098.5 R17.2@1437.5,1101 ; U1.21@1416.69,1480.53 1416.69,1121.8 R17.2@1437.5,1101 ; J1.1@3086,558 3054,558 2981,485 2289,485 1876.5,897.5 1778.18,897.5 1574.68,1101 R17.2@1437.5,1101
CLR_GPIO1: C5.1 J3.2 J8.9 R2.1 U1.20 | length 1952
  L1-TOP w8: C5.1@1334.43,1250 v3(1370,1250)
  L1-TOP w9: J3.2@1125,1262.48 J3.2@1135,1262.48 1147.48,1250 C5.1@1334.43,1250 ; R2.1@1292,1466.5 1294.5,1464 1300.5,1470 v3(1370,1470) 1370,1495 1381.12,1506.12 U1.20@1391.1,1506.12
  L4-BOTTOM w9: J8.9@262,2014 853.73,2014 1370,1497.73 v3(1370,1470) v3(1370,1250)
CS_GPIO8: J8.2 R15.2 TP7.1 U1.14 | length 1432.6
  L1-TOP w8: J8.2@162,1614 J8.2@166,1610
  L1-TOP w9: J8.2@166,1610 166,1574 270,1470 TP7.1@526,1470 915.5,1470 R15.2@919,1466.5 919,1562 981.23,1624.23 U1.14@1391.1,1624.23
EXT_REF: J7.1 J11.3 | length 2009.6
  L1-TOP w20: J7.1@185,1245 J7.1@198.39,1258.39 ; J7.1@185,1258.39 J7.1@198.39,1258.39 ; v3(1550,1040) 1508,998 865,998 588,1275 290,1275 273.39,1258.39 J7.1@198.39,1258.39 ; v3(1895,1161) J11.3@1895,1252.52
  L4-BOTTOM w20: v3(1550,1040) 1774,1040 v3(1895,1161)
EXT_VIO: J7.4 J10.3 | length 444.4
  L1-TOP w30: J7.4@185,831.61 198.39,845 407,845 420,832 J10.3@618.5,832
GND: C1.2 C2.2 C3.2 C4.2 C5.2 C6.2 C7.2 C8.2 C10.2 C11.2 C12.2 C14.2 C15.2 C16.2 C17.2 C18.2 C19.2 J1.9 J1.11 J1.13 J1.15 J1.17 J1.19 J1.21 J1.23 J1.25 J1.27 J1.29 J1.31 J2.1 J3.1 J4.2 J4.3 J4.4 J4.5 J5.2 J5.3 J5.4 J5.5 J6.2 J6.3 J6.4 J6.5 J7.3 J8.6 J9.1 J12.1 TP1.1 TP2.1 U1.10 U1.36 U1.41@1505.28,1594.7 U2.4 | length 3247.9
  L1-TOP w9: U1.10@1416.69,1708.88 1416.69,1683.28 U1.41@1505.28,1594.7 ; U1.36@1619.45,1604.54 1638.39,1604.54 1638.77,1604.17 1660.27,1604.17 1671.11,1615 v3(1695,1615)
  L1-TOP w10: J1.31@3054,2058 J1.31@3086,2058
  L1-TOP w15: v2(1665,1291.5) 1665,1339 1669,1335 v2(1715,1335) ; v2(1770,1980) 1770,1925 1782.5,1912.5 1786.75,1916.75 1791,1921 1800,1921 1810,1931 v2(1810,1980) ; C1.2@1883.5,1599 v3@1883.5,1637.5
  L1-TOP w20: v2(370,655) C6.2@425,655 v2(485,655) ; v4(392.09,367.91) C8.2@470,367.91 547.91,367.91 v4(548.96,368.96) ; v2(450,1225) 501,1225 C11.2@503,1223 ; C11.2@504,1223 563,1223 v1(565,1225) ; v2(655,385) C7.2@655,437.91 657.91,435 v2(735,435) ; C4.2@825,1158.5 873.5,1158.5 872.01,1160 v2(870,1160) ; v2@960,1150 v2(961.5,1150) J2.1@1030,1150 ; v2(1170,1147.52) J3.1@1235,1147.52 ; v4(1228,1766) 1229,1767 C3.2@1271.5,1767 ; v2(1286,875) J12.1@1286,774.02 ; v2(1287,686) 1287,710 1277,720 1286,729 J12.1@1286,774.02 ; C5.2@1322.5,1185 C5.2@1330,1185 ; C5.2@1330,1188.5 v2(1385,1188.5) ; v2(1335,775) 1287,775 J12.1@1286,774.02 ; C14.2@1668,1849 1668,1883 v3(1683,1898) ; C2.2@1768,1748.5 v2(1768,1795) ; C12.2@1773,1287 v2(1828,1287) ; v3(1909.5,1531.5) C16.2@1948,1531.5 1970.16,1509.34 U2.4@2019.36,1509.34 ; v3(2054,1905) J9.1@2168,1905 ; v6(2171.5,1390.5) C17.2@2171.5,1439 ; v6(2511,1434) 2511.5,1434.5 C19.2@2511.5,1483 2532,1503.5 C18.2@2532,1559 ; v4(2998,958) J1.9@3086,958 ; v4(2998,1058) J1.11@3086,1058 ; v4(2998,1158) J1.13@3086,1158 ; v4(2998,1258) J1.15@3086,1258 ; v4(2998,1358) J1.17@3086,1358 ; v4(2998,1458) J1.19@3086,1458 ; v4(2998,1558) J1.21@3086,1558 ; v4(2998,1658) J1.23@3086,1658 ; v4(2998,1758) J1.25@3086,1758 ; v4(2998,1858) J1.27@3086,1858 ; v4(2998,1958) J1.29@3086,1958 ; v4(3005,2055) J1.31@3093,2055
  other v1: 2175,360 2295,360 2395,360 2515,360 2050,380 2390,610 2490,610 2610,610 2390,700 2490,700 2610,700 2490,795 2610,795 2140,810 2135,910 2285,1140 2360,1140 2285,1240 2360,1240 2720,1340 2640,1345 705,1365 95,1390 185,1390 2640,1430 2715,1430 100,1475 185,1480 705,1525 820,1525 685,1655 880,1750 680,1780 1020,1780 800,1830 940,1860 1165,1890 1280,1890 1391.1,1895 1030,1990 1165,1990 1280,1990 1391.1,1995 1030,2085 1165,2085 1280,2085 1400,2085 1515,2085 1030,2185 1165,2185 1280,2185 1400,2185 1515,2185 2810,2190 2900,2190 3100,2190 1795,2210 1910,2210 2125,2220 1795,2295 1910,2295 2125,2305
  other v3: 1884,1635
  other v5: 1476.54,1515.96 1534.02,1515.96 1426.54,1565.96 1476.54,1565.96 1534.02,1565.96 1584.02,1565.96 1426.54,1623.44 1476.54,1623.44 1534.02,1623.44 1584.02,1623.44 1476.54,1673.44 1534.02,1673.44
LDAC_GPIO3: J8.7 R16.2 TP9.1 U1.18 | length 1650.6
  L1-TOP w9: J8.7@262,1914 389,1914 440,1965 TP9.1@525,1965 ; R16.2@1168,1466.5 1173.49,1471.99 1165,1480.47 v3(1165,1545) 1390.62,1545 U1.18@1391.1,1545.49
  L4-BOTTOM w9: J8.7@262,1914 796,1914 v3(1165,1545)
MISO_RXD: J8.3 R7.1 TP6.1 | length 1095.5
  L1-TOP w9: J8.3@262,1714 388,1840 TP6.1@525,1840 695,1840 837,1698 R7.1@1246.5,1698
MOSI_TXD: J8.4 TP8.1 U1.13 | length 1380.4
  L1-TOP w9: J8.4@162,1714 210,1666 210,1583 238,1555 370,1555 408,1593 TP8.1@526,1593 763,1593 813.91,1643.91 U1.13@1391.1,1643.91
NetC1_1: C1.1 L1.2 TP4.1 U1.37 | length 1359.3
  L1-TOP w8: U1.37@1619.45,1624.23 1647,1624.23
  L1-TOP w15: 1647,1624.04 1652.04,1624.04 1675,1647 1770,1647 1814.25,1602.75 1816.75,1602.75 C1.1@1820.5,1599 1820.5,1603.5 1834,1617 L1.2@1834,1661.5 1876.5,1661.5 v3(1895,1680)
  L4-BOTTOM w15: v3(1895,1680) 2180,1680 TP4.1@2680,2180
NetC9_1: C9.1 U1.34 | length 157.3
  L1-TOP w9: U1.34@1619.45,1565.17 1709.33,1565.17 C9.1@1757,1517.5
NetC10_1: C10.1 C12.1 J12.2 TP13.1 U1.32 U1.39 | length 2343.4
  L1-TOP w9: U1.32@1619.45,1525.8 1639.2,1525.8 1662.5,1502.5 ; U1.39@1619.45,1663.6 1632.6,1663.6 1634.99,1665.99 1635.23,1665.99 1643.64,1674.39 1643.64,1674.64 1648,1679
  L1-TOP w15: J12.2@1186,934 J12.2@1186,888.98 1194.02,897 v2(1237,897) 1256,916 1537.15,916 1719.15,734 1938,734 2252,420 2384,420 TP13.1@2634,170 ; J12.2@1193.02,848.02 v2(1236,848.02) ; 1648,1679.35 1670.65,1702 1714,1702 1727,1715 1727,1822 1746,1841 C10.1@1791,1841 ; v3(1848,1824) 1811,1824 1794,1841 C10.1@1791,1841 ; v3(1848,1855) 1805,1855 C10.1@1791,1841
  other v3: 1828,1363 1828,1399
NetC16_1: C16.1 L2.2 U2.2 | length 143.9
  L1-TOP w10: L2.2@1949,1660.5 1948,1659.5 C16.1@1948,1594.5 1972.76,1594.5 1987.61,1609.34 U2.2@2019.36,1609.34
NetC17_1: C17.1 U2.5 | length 70.6
  L1-TOP w10: U2.5@2233.93,1509.34 2233.93,1439.56 C17.1@2234.5,1439
NetC18_1: C18.1 R18.1 | length 73.5
  L1-TOP w10: R18.1@2378.5,1559 C18.1@2452,1559
NetC19_1: C19.1 R19.1 | length 71.4
  L1-TOP w10: R19.1@2377.5,1482 2447.5,1482 C19.1@2448.5,1483
NetJ1_3: J1.3 U1.22 | length 2279.1
  L1-TOP w9: U1.22@1436.38,1480.53 1436.38,1263.17 1785.17,914.38 1892.62,914.38 2293,514 2941,514 2984.5,557.5 2984.5,629.5 3013,658 J1.3@3086,658
NetJ4_1: J4.1 R12.2 TP14.1 U1.15 | length 2488.7
  L1-TOP w8: R12.2@981,1484 R12.2@986,1479
  L1-TOP w9: R12.2@981,1466 981,1484 v3(981,1578) 1007.54,1604.54 U1.15@1391.1,1604.54 ; J4.1@1840,500 1840,220 TP14.1@1866,194
  L4-BOTTOM w9: v3(981,1578) 1087.51,1578 1142.88,1522.63 1183.73,1522.63 1221.23,1560.12 1283.74,1560.12 1345,1498.86 1345,1170 1840,675 J4.1@1840,500
NetJ5_1: J5.1 R13.2 TP15.1 U1.16 | length 2087.8
  L1-TOP w9: R13.2@1043,1466.5 v3(1043,1516) 1111.86,1584.86 U1.16@1391.1,1584.86 ; TP15.1@1389,194 1389.99,194.99 J5.1@1389.99,500
  L4-BOTTOM w9: v3(1043,1516) 1057,1530 1111.64,1530 1135.89,1505.75 1190.72,1505.75 1228.22,1543.25 1276.75,1543.25 1325,1495 1325,1160 1390,1095 J5.1@1389.99,500
NetJ6_1: J6.1 R14.2 TP16.1 U1.17 | length 2062.5
  L1-TOP w8: v3(1105,1505) 1105,1473.5 1102,1470.5 R14.2@1106,1466.5
  L1-TOP w9: TP16.1@888,194 915,221 J6.1@915,500 ; v3(1105,1505) 1105,1527.99 1144.38,1567.37 1174.27,1567.37 1176.47,1565.17 U1.17@1391.1,1565.17
  L4-BOTTOM w9: J6.1@915,500 915,665 1135,885 1135,1040 1301.37,1206.37 1301.37,1485.27 1264.27,1522.37 1231.21,1522.37 1197.71,1488.88 1121.12,1488.88 v3(1105,1505)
